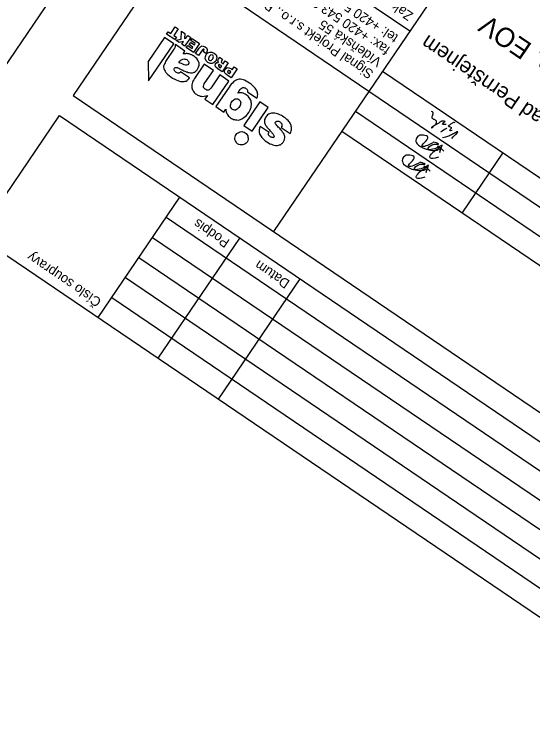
# Model space of a CAD drawing. Extents: x -621058 to -620110, y -1122807 to -1122030.
# Drawn here: x -621002.7 to -620949.2, y -1122263.7 to -1122190.1 of the extents above; entities that cross this region are included whole.
import ezdxf

# ---------------------------------------------------------------- set-up
doc = ezdxf.new("R2010")
doc.units = 0
for name, color, linetype in [('Default', 7, 'Continuous'), ('Info o rozpiskách', 7, 'Continuous'), ('LICHE', 7, 'Continuous'), ('Podpisy', 7, 'Continuous'), ('popis', 7, 'Continuous'), ('Ramečky', 7, 'Continuous'), ('RÁMY', 7, 'Continuous'), ('Text', 7, 'Continuous'), ('Text barevný', 7, 'Continuous')]:
    doc.layers.add(name, color=color, linetype=linetype)

# ---------------------------------------------------------------- blocks, each defined once
blk = doc.blocks.new('A$C65FD2E33_1')
at = {"layer": 'popis'}
for points in [[(-0.001696, 0.001402), (-0.001243, 0.00199), (-0.000783, 0.002198), (-0.00058, 0.001995), (-0.000655, 0.001241), (-0.001176, -0.000273), (-0.001696, 0.001402), (-0.001176, -0.000273)], [(0, 0), (0.000429, 0.000991), (0.001306, 0.001883), (0.000916, 0.000325), (0.00104, -0.00033), (0.00205, 0.000162), (0.002331, 0.000523), (0.002284, 0.001298), (0.001686, 0.001657), (0.000024, 0.001491), (-0.001834, 0.000276), (0, 0), (-0.001834, 0.000276)], [(-0.001176, -0.000273), (-0.00069, 0.000816), (0.000494, 0.001844), (0, 0), (-0.001176, -0.000273), (0, 0)]]:
    blk.add_open_spline(points, degree=3, dxfattribs=at)
blk = doc.blocks.new('podpis_vyvoda')
at = {"layer": 'Default'}
for points, degree in [([(0.027, 0.238), (0.019, 0.149), (-0.001, 0.052), (-0.009, -0.025), (0.03, 0.048), (0.089, 0.161), (0.154, 0.255), (0.197, 0.319), (0.239, 0.357)], 3), ([(0.289, 0.083), (0.328, 0.161), (0.348, 0.206), (0.366, 0.257)], 2), ([(0.361, 0.009), (0.395, 0.041), (0.415, 0.059), (0.44, 0.059), (0.446, 0.056), (0.449, 0.046), (0.448, 0.031), (0.447, 0.012), (0.439, -0.011), (0.429, -0.026), (0.425, -0.037), (0.431, -0.039), (0.466, -0.022), (0.498, 0), (0.518, 0.019), (0.527, 0.042), (0.531, 0.068), (0.542, 0.096), (0.556, 0.126), (0.582, 0.173), (0.6, 0.207), (0.62, 0.245), (0.63, 0.266), (0.634, 0.282), (0.636, 0.302), (0.629, 0.305), (0.62, 0.291), (0.614, 0.271), (0.61, 0.243), (0.596, 0.181), (0.594, 0.151), (0.596, 0.113), (0.605, 0.097), (0.62, 0.085), (0.645, 0.077), (0.675, 0.079), (0.701, 0.085), (0.734, 0.088), (0.757, 0.086), (0.775, 0.068), (0.783, 0.042), (0.788, 0.018), (0.795, -0.004), (0.804, -0.027), (0.816, -0.045), (0.832, -0.054), (0.848, -0.058), (0.874, -0.055)], 3), ([(0.141, 0.058), (0.176, 0.089), (0.196, 0.096), (0.203, 0.087), (0.195, 0.044), (0.19, 0.021), (0.197, 0.004), (0.217, 0.007), (0.27, 0.019), (0.283, 0.019), (0.288, 0.002), (0.28, -0.031), (0.269, -0.069), (0.243, -0.119), (0.227, -0.15), (0.219, -0.158), (0.203, -0.155)], 3)]:
    blk.add_open_spline(points, degree=degree, dxfattribs=at)

msp = doc.modelspace()

# ---------------------------------------------------------------- linework, layer by layer
at = {"layer": 'Info o rozpiskách'}
for points in [[(-620986.09, -1122192.714), (-620986.939, -1122192.137), (-620986.776, -1122191.898), (-620986.506, -1122192.081), (-620986.045, -1122191.402), (-620985.744, -1122191.607), (-620986.205, -1122192.286), (-620985.927, -1122192.474), (-620986.09, -1122192.714)], [(-620985.079, -1122193.4), (-620985.388, -1122193.191), (-620985.188, -1122192.897), (-620985.65, -1122193.012), (-620986.005, -1122192.771), (-620985.429, -1122192.654), (-620985.42, -1122191.827), (-620985.057, -1122192.073), (-620985.08, -1122192.588), (-620984.963, -1122192.566), (-620984.764, -1122192.272), (-620984.455, -1122192.482), (-620985.079, -1122193.4)], [(-620984.161, -1122194.024), (-620984.909, -1122193.515), (-620984.768, -1122193.307), (-620984.32, -1122193.611), (-620984.226, -1122193.472), (-620984.604, -1122193.215), (-620984.457, -1122192.999), (-620984.079, -1122193.256), (-620983.984, -1122193.117), (-620984.455, -1122192.797), (-620984.309, -1122192.581), (-620983.537, -1122193.105), (-620984.161, -1122194.024)], [(-620983.667, -1122194.359), (-620983.968, -1122194.155), (-620983.58, -1122193.584), (-620983.428, -1122193.427), (-620983.26, -1122193.361), (-620982.973, -1122193.454), (-620982.83, -1122193.575), (-620982.756, -1122193.715), (-620982.757, -1122193.883), (-620982.836, -1122194.066), (-620982.891, -1122194.13), (-620983.161, -1122193.947), (-620983.072, -1122193.782), (-620983.102, -1122193.694), (-620983.177, -1122193.688), (-620983.253, -1122193.749), (-620983.667, -1122194.359)], [(-620982.687, -1122195.058), (-620982.875, -1122194.886), (-620982.963, -1122194.668), (-620982.943, -1122194.456), (-620982.854, -1122194.257), (-620982.692, -1122194.085), (-620982.494, -1122193.994), (-620982.267, -1122193.991), (-620982.032, -1122194.094), (-620981.842, -1122194.279), (-620981.759, -1122194.505), (-620981.786, -1122194.711), (-620981.881, -1122194.918), (-620982.038, -1122195.082), (-620982.23, -1122195.166), (-620982.458, -1122195.169), (-620982.687, -1122195.058)], [(-620982.535, -1122194.834), (-620982.448, -1122194.871), (-620982.362, -1122194.862), (-620982.185, -1122194.7), (-620982.095, -1122194.468), (-620982.184, -1122194.317), (-620982.383, -1122194.295), (-620982.537, -1122194.439), (-620982.622, -1122194.663), (-620982.61, -1122194.761), (-620982.535, -1122194.834)], [(-620981.221, -1122196.02), (-620981.668, -1122195.716), (-620981.858, -1122195.565), (-620981.948, -1122195.414), (-620981.891, -1122195.182), (-620981.746, -1122195.066), (-620981.585, -1122195.062), (-620981.653, -1122194.881), (-620981.572, -1122194.711), (-620981.524, -1122194.641), (-620981.485, -1122194.567), (-620981.493, -1122194.528), (-620981.477, -1122194.504), (-620981.168, -1122194.714), (-620981.263, -1122194.887), (-620981.308, -1122195.07), (-620981.252, -1122195.12), (-620981.164, -1122195.19), (-620981.118, -1122195.222), (-620980.898, -1122194.898), (-620980.597, -1122195.102), (-620981.221, -1122196.02)], [(-620981.38, -1122195.608), (-620981.254, -1122195.422), (-620981.386, -1122195.333), (-620981.515, -1122195.291), (-620981.574, -1122195.329), (-620981.591, -1122195.419), (-620981.527, -1122195.508), (-620981.38, -1122195.608)], [(-620980.295, -1122196.649), (-620980.735, -1122196.351), (-620980.894, -1122196.22), (-620980.976, -1122196.074), (-620980.984, -1122195.921), (-620980.908, -1122195.759), (-620980.684, -1122195.595), (-620980.513, -1122195.61), (-620980.32, -1122195.707), (-620980.166, -1122195.812), (-620979.972, -1122195.526), (-620979.671, -1122195.731), (-620980.295, -1122196.649)], [(-620980.454, -1122196.237), (-620980.313, -1122196.028), (-620980.444, -1122195.939), (-620980.537, -1122195.91), (-620980.633, -1122195.968), (-620980.649, -1122196.059), (-620980.539, -1122196.179), (-620980.454, -1122196.237)], [(-620979.613, -1122203.449), (-620979.716, -1122203.368), (-620979.782, -1122203.267), (-620979.838, -1122203.15), (-620979.891, -1122203.012), (-620979.895, -1122202.886), (-620979.874, -1122202.754), (-620979.839, -1122202.62), (-620979.773, -1122202.506), (-620979.692, -1122202.403), (-620979.575, -1122202.314), (-620979.46, -1122202.245), (-620979.352, -1122202.217), (-620979.194, -1122202.2), (-620979.075, -1122202.225), (-620978.956, -1122202.249), (-620978.843, -1122202.315), (-620978.724, -1122202.407), (-620978.65, -1122202.513), (-620978.568, -1122202.625), (-620978.549, -1122202.763), (-620978.527, -1122202.879), (-620978.525, -1122203.027), (-620978.573, -1122203.163), (-620978.623, -1122203.287), (-620978.72, -1122203.38), (-620978.824, -1122203.466), (-620978.962, -1122203.52), (-620979.089, -1122203.557), (-620979.213, -1122203.574), (-620979.358, -1122203.555), (-620979.484, -1122203.526), (-620979.613, -1122203.449)]]:
    msp.add_lwpolyline(points, dxfattribs=at)
at = {"layer": 'popis'}
for points in [[(-620988.796, -1122196.965), (-620986.192, -1122193.129), (-620987.149, -1122192.479), (-620988.841, -1122194.972), (-620988.796, -1122196.965)], [(-620984.576, -1122196.662), (-620985.495, -1122196.038), (-620985.55, -1122196.103), (-620985.602, -1122196.146), (-620985.659, -1122196.164), (-620985.718, -1122196.168), (-620985.786, -1122196.168), (-620985.858, -1122196.141), (-620985.912, -1122196.105), (-620985.974, -1122196.063), (-620986.043, -1122196.016), (-620986.107, -1122195.96), (-620986.14, -1122195.893), (-620986.161, -1122195.857), (-620986.171, -1122195.805), (-620986.18, -1122195.753), (-620986.154, -1122195.714), (-620986.144, -1122195.665), (-620986.102, -1122195.637), (-620986.063, -1122195.596), (-620986.003, -1122195.591), (-620985.944, -1122195.587), (-620985.869, -1122195.592), (-620985.781, -1122195.63), (-620985.686, -1122195.672), (-620985.59, -1122195.714), (-620985.492, -1122195.769), (-620985.382, -1122195.822), (-620985.278, -1122195.869), (-620985.168, -1122195.922), (-620985.052, -1122195.967), (-620984.941, -1122196.02), (-620984.835, -1122196.046), (-620984.732, -1122196.094), (-620984.613, -1122196.118), (-620984.489, -1122196.135), (-620984.37, -1122196.125), (-620984.274, -1122196.134), (-620984.178, -1122196.109), (-620984.098, -1122196.073), (-620984.041, -1122196.056), (-620983.971, -1122196.002), (-620983.914, -1122195.951), (-620983.851, -1122195.892), (-620983.801, -1122195.835), (-620983.754, -1122195.766), (-620983.641, -1122195.549), (-620983.593, -1122195.345), (-620983.598, -1122195.138), (-620983.649, -1122194.98), (-620983.728, -1122194.814), (-620983.838, -1122194.66), (-620983.948, -1122194.54), (-620984.081, -1122194.438), (-620984.143, -1122194.397), (-620984.202, -1122194.367), (-620984.264, -1122194.326), (-620984.344, -1122194.294), (-620984.396, -1122194.27), (-620984.47, -1122194.231), (-620984.543, -1122194.204), (-620984.607, -1122194.183), (-620984.682, -1122194.177), (-620984.757, -1122194.171), (-620984.827, -1122194.158), (-620984.914, -1122194.154), (-620984.987, -1122194.161), (-620985.065, -1122194.177), (-620985.158, -1122194.181), (-620985.23, -1122194.188), (-620985.052, -1122193.892), (-620986.04, -1122193.221), (-620986.066, -1122193.26), (-620986.049, -1122193.35), (-620986.052, -1122193.405), (-620986.055, -1122193.459), (-620986.076, -1122193.49), (-620986.092, -1122193.547), (-620986.113, -1122193.578), (-620986.144, -1122193.624), (-620986.186, -1122193.685), (-620986.993, -1122194.874), (-620987.061, -1122194.974), (-620987.106, -1122195.09), (-620987.154, -1122195.193), (-620987.201, -1122195.296), (-620987.23, -1122195.389), (-620987.249, -1122195.467), (-620987.258, -1122195.562), (-620987.236, -1122195.679), (-620987.203, -1122195.78), (-620987.165, -1122195.874), (-620987.104, -1122195.983), (-620987.029, -1122196.09), (-620986.937, -1122196.186), (-620986.809, -1122196.296), (-620986.673, -1122196.411), (-620986.519, -1122196.549), (-620986.32, -1122196.673), (-620986.109, -1122196.794), (-620985.947, -1122196.87), (-620985.785, -1122196.946), (-620985.627, -1122196.997), (-620985.501, -1122197.026), (-620985.364, -1122197.041), (-620985.242, -1122197.044), (-620985.123, -1122197.035), (-620985.027, -1122197.01), (-620984.918, -1122196.982), (-620984.835, -1122196.926), (-620984.778, -1122196.875), (-620984.702, -1122196.814), (-620984.634, -1122196.747), (-620984.576, -1122196.662)], [(-620985.683, -1122195.087), (-620985.678, -1122195.079), (-620985.662, -1122195.056), (-620985.652, -1122195.041), (-620985.563, -1122194.943), (-620985.482, -1122194.84), (-620985.391, -1122194.789), (-620985.282, -1122194.728), (-620985.173, -1122194.701), (-620985.069, -1122194.714), (-620984.958, -1122194.733), (-620984.858, -1122194.768), (-620984.788, -1122194.815), (-620984.753, -1122194.862), (-620984.722, -1122194.917), (-620984.691, -1122194.971), (-620984.666, -1122195.034), (-620984.654, -1122195.098), (-620984.649, -1122195.158), (-620984.683, -1122195.225), (-620984.767, -1122195.315), (-620984.873, -1122195.355), (-620984.997, -1122195.339), (-620985.118, -1122195.302), (-620985.27, -1122195.243), (-620985.397, -1122195.18), (-620985.546, -1122195.135), (-620985.683, -1122195.087)], [(-620982.163, -1122199.417), (-620980.512, -1122196.986), (-620981.438, -1122196.357), (-620982.282, -1122197.6), (-620982.371, -1122197.731), (-620982.478, -1122197.839), (-620982.564, -1122197.882), (-620982.637, -1122197.923), (-620982.717, -1122197.925), (-620982.8, -1122197.914), (-620982.882, -1122197.869), (-620982.97, -1122197.832), (-620983.036, -1122197.764), (-620983.08, -1122197.712), (-620983.134, -1122197.642), (-620983.141, -1122197.569), (-620983.135, -1122197.494), (-620983.119, -1122197.404), (-620983.061, -1122197.285), (-620982.987, -1122197.177), (-620982.117, -1122195.896), (-620983.059, -1122195.257), (-620984.055, -1122196.723), (-620984.144, -1122196.854), (-620984.22, -1122196.983), (-620984.275, -1122197.114), (-620984.31, -1122197.249), (-620984.335, -1122197.368), (-620984.346, -1122197.484), (-620984.324, -1122197.6), (-620984.324, -1122197.702), (-620984.299, -1122197.797), (-620984.266, -1122197.898), (-620984.205, -1122197.974), (-620984.154, -1122198.065), (-620984.082, -1122198.159), (-620984.016, -1122198.227), (-620983.949, -1122198.294), (-620983.857, -1122198.357), (-620983.741, -1122198.436), (-620983.604, -1122198.484), (-620983.493, -1122198.536), (-620983.349, -1122198.556), (-620983.212, -1122198.57), (-620983.059, -1122198.561), (-620982.906, -1122198.518), (-620982.732, -1122198.478), (-620982.989, -1122198.857), (-620982.163, -1122199.417)], [(-620981.034, -1122200.195), (-620980.83, -1122199.894), (-620980.818, -1122200.026), (-620980.788, -1122200.148), (-620980.75, -1122200.275), (-620980.692, -1122200.405), (-620980.623, -1122200.52), (-620980.546, -1122200.606), (-620980.456, -1122200.689), (-620980.346, -1122200.775), (-620980.232, -1122200.841), (-620980.15, -1122200.886), (-620980.031, -1122200.944), (-620979.928, -1122200.958), (-620979.82, -1122200.997), (-620979.693, -1122200.993), (-620979.569, -1122201.01), (-620979.439, -1122200.985), (-620979.325, -1122200.95), (-620979.195, -1122200.892), (-620979.073, -1122200.828), (-620978.966, -1122200.754), (-620978.831, -1122200.654), (-620978.706, -1122200.536), (-620978.586, -1122200.392), (-620978.475, -1122200.23), (-620978.386, -1122200.099), (-620978.323, -1122199.973), (-620978.281, -1122199.844), (-620978.233, -1122199.707), (-620978.203, -1122199.581), (-620978.189, -1122199.443), (-620978.201, -1122199.311), (-620978.21, -1122199.192), (-620978.233, -1122199.076), (-620978.26, -1122198.967), (-620978.316, -1122198.85), (-620978.382, -1122198.749), (-620978.449, -1122198.647), (-620978.534, -1122198.556), (-620978.623, -1122198.472), (-620978.732, -1122198.399), (-620978.824, -1122198.336), (-620978.919, -1122198.294), (-620979.038, -1122198.236), (-620979.157, -1122198.211), (-620979.268, -1122198.192), (-620979.389, -1122198.189), (-620979.488, -1122198.201), (-620979.61, -1122198.231), (-620979.458, -1122198.007), (-620979.348, -1122197.845), (-620979.243, -1122197.758), (-620979.147, -1122197.699), (-620979.074, -1122197.658), (-620978.989, -1122197.649), (-620978.917, -1122197.675), (-620978.832, -1122197.699), (-620978.755, -1122197.752), (-620978.716, -1122197.778), (-620978.667, -1122197.822), (-620978.631, -1122197.869), (-620978.603, -1122197.911), (-620978.601, -1122197.957), (-620978.583, -1122198.014), (-620978.596, -1122198.051), (-620978.607, -1122198.1), (-620977.627, -1122198.765), (-620977.567, -1122198.626), (-620977.555, -1122198.51), (-620977.546, -1122198.38), (-620977.553, -1122198.274), (-620977.565, -1122198.142), (-620977.626, -1122198.033), (-620977.685, -1122197.937), (-620977.743, -1122197.807), (-620977.815, -1122197.713), (-620977.9, -1122197.622), (-620977.976, -1122197.536), (-620978.069, -1122197.44), (-620978.148, -1122197.374), (-620978.22, -1122197.314), (-620978.308, -1122197.243), (-620978.377, -1122197.196), (-620978.552, -1122197.088), (-620978.725, -1122196.994), (-620978.895, -1122196.912), (-620979.039, -1122196.859), (-620979.188, -1122196.814), (-620979.333, -1122196.795), (-620979.46, -1122196.799), (-620979.582, -1122196.829), (-620979.709, -1122196.866), (-620979.826, -1122196.922), (-620979.94, -1122196.991), (-620980.058, -1122197.081), (-620980.157, -1122197.194), (-620980.29, -1122197.307), (-620980.389, -1122197.453), (-620980.505, -1122197.623), (-620981.867, -1122199.629), (-620981.034, -1122200.195)], [(-620980.147, -1122199.918), (-620980.221, -1122199.845), (-620980.29, -1122199.764), (-620980.341, -1122199.673), (-620980.366, -1122199.577), (-620980.353, -1122199.474), (-620980.326, -1122199.368), (-620980.283, -1122199.239), (-620980.204, -1122199.123), (-620980.136, -1122199.023), (-620980.043, -1122198.951), (-620979.957, -1122198.874), (-620979.871, -1122198.832), (-620979.793, -1122198.816), (-620979.687, -1122198.81), (-620979.602, -1122198.834), (-620979.504, -1122198.889), (-620979.417, -1122198.959), (-620979.355, -1122199.035), (-620979.315, -1122199.141), (-620979.295, -1122199.211), (-620979.308, -1122199.315), (-620979.317, -1122199.411), (-620979.365, -1122199.514), (-620979.425, -1122199.619), (-620979.506, -1122199.722), (-620979.59, -1122199.812), (-620979.668, -1122199.894), (-620979.756, -1122199.958), (-620979.832, -1122199.986), (-620979.943, -1122200), (-620980.036, -1122199.971), (-620980.147, -1122199.918)], [(-620978.12, -1122202.163), (-620976.469, -1122199.732), (-620977.333, -1122199.145), (-620978.984, -1122201.577), (-620978.12, -1122202.163)], [(-620976.377, -1122202.287), (-620977.287, -1122201.669), (-620977.317, -1122201.761), (-620977.348, -1122201.842), (-620977.372, -1122201.926), (-620977.389, -1122202.017), (-620977.392, -1122202.105), (-620977.393, -1122202.206), (-620977.389, -1122202.299), (-620977.366, -1122202.416), (-620977.323, -1122202.501), (-620977.27, -1122202.605), (-620977.203, -1122202.707), (-620977.121, -1122202.819), (-620977.021, -1122202.92), (-620976.906, -1122203.033), (-620976.77, -1122203.148), (-620976.613, -1122203.265), (-620976.446, -1122203.368), (-620976.281, -1122203.457), (-620976.129, -1122203.516), (-620975.982, -1122203.581), (-620975.847, -1122203.616), (-620975.723, -1122203.633), (-620975.61, -1122203.631), (-620975.496, -1122203.63), (-620975.384, -1122203.615), (-620975.296, -1122203.585), (-620975.208, -1122203.554), (-620975.138, -1122203.501), (-620975.054, -1122203.444), (-620974.992, -1122203.386), (-620974.94, -1122203.342), (-620974.882, -1122203.257), (-620974.821, -1122203.118), (-620974.776, -1122202.968), (-620974.751, -1122202.849), (-620974.761, -1122202.697), (-620974.793, -1122202.595), (-620974.831, -1122202.468), (-620974.9, -1122202.354), (-620974.987, -1122202.25), (-620975.069, -1122202.138), (-620975.156, -1122202.034), (-620975.243, -1122201.929), (-620975.33, -1122201.825), (-620975.428, -1122201.736), (-620975.51, -1122201.658), (-620975.587, -1122201.572), (-620975.645, -1122201.475), (-620975.709, -1122201.387), (-620975.727, -1122201.33), (-620975.732, -1122201.27), (-620975.713, -1122201.227), (-620975.65, -1122201.168), (-620975.606, -1122201.153), (-620975.565, -1122201.125), (-620975.497, -1122201.125), (-620975.422, -1122201.131), (-620975.373, -1122201.142), (-620975.309, -1122201.163), (-620975.255, -1122201.2), (-620975.201, -1122201.236), (-620975.15, -1122201.294), (-620975.096, -1122201.364), (-620975.073, -1122201.413), (-620975.056, -1122201.504), (-620975.048, -1122201.576), (-620975.07, -1122201.674), (-620975.11, -1122201.783), (-620974.207, -1122202.396), (-620974.138, -1122202.262), (-620974.096, -1122202.133), (-620974.072, -1122202.014), (-620974.065, -1122201.906), (-620974.067, -1122201.792), (-620974.082, -1122201.68), (-620974.104, -1122201.564), (-620974.144, -1122201.458), (-620974.206, -1122201.348), (-620974.267, -1122201.239), (-620974.338, -1122201.145), (-620974.418, -1122201.047), (-620974.528, -1122200.96), (-620974.613, -1122200.869), (-620974.708, -1122200.793), (-620974.839, -1122200.704), (-620974.976, -1122200.622), (-620975.107, -1122200.533), (-620975.246, -1122200.473), (-620975.385, -1122200.412), (-620975.517, -1122200.357), (-620975.643, -1122200.327), (-620975.78, -1122200.313), (-620975.892, -1122200.294), (-620976.013, -1122200.29), (-620976.137, -1122200.307), (-620976.233, -1122200.332), (-620976.334, -1122200.365), (-620976.433, -1122200.411), (-620976.527, -1122200.482), (-620976.598, -1122200.57), (-620976.66, -1122200.662), (-620976.676, -1122200.685), (-620976.692, -1122200.708), (-620976.708, -1122200.732), (-620976.723, -1122200.755), (-620976.744, -1122200.786), (-620976.76, -1122200.809), (-620976.771, -1122200.824), (-620976.781, -1122200.84), (-620976.841, -1122200.945), (-620976.855, -1122201.049), (-620976.853, -1122201.163), (-620976.829, -1122201.259), (-620976.804, -1122201.354), (-620976.768, -1122201.469), (-620976.725, -1122201.554), (-620976.653, -1122201.648), (-620976.589, -1122201.737), (-620976.518, -1122201.831), (-620976.446, -1122201.924), (-620976.372, -1122201.997), (-620976.287, -1122202.089), (-620976.218, -1122202.169), (-620976.136, -1122202.248), (-620976.074, -1122202.323), (-620976.018, -1122202.406), (-620975.959, -1122202.469), (-620975.926, -1122202.537), (-620975.883, -1122202.589), (-620975.867, -1122202.633), (-620975.842, -1122202.695), (-620975.842, -1122202.729), (-620975.863, -1122202.759), (-620975.884, -1122202.79), (-620975.921, -1122202.811), (-620975.972, -1122202.821), (-620976.014, -1122202.815), (-620976.066, -1122202.825), (-620976.12, -1122202.789), (-620976.192, -1122202.762), (-620976.246, -1122202.725), (-620976.308, -1122202.683), (-620976.351, -1122202.631), (-620976.392, -1122202.592), (-620976.423, -1122202.537), (-620976.427, -1122202.478), (-620976.417, -1122202.429), (-620976.416, -1122202.362), (-620976.377, -1122202.287)]]:
    msp.add_lwpolyline(points, dxfattribs=at)
at = {"layer": 'Ramečky'}
for p, q in [((-620972.705, -1122163.327), (-620996.583, -1122198.486)), ((-620952.024, -1122177.373), (-620975.901, -1122212.531)), ((-620961.856, -1122191.85), (-620982.537, -1122177.804)), ((-620910.893, -1122232.505), (-620964.665, -1122195.986)), ((-620912.297, -1122234.573), (-620966.069, -1122198.054)), ((-620996.583, -1122198.486), (-620922.129, -1122249.05)), ((-620913.702, -1122236.641), (-620967.474, -1122200.123)), ((-621006.414, -1122212.963), (-620997.987, -1122200.554)), ((-620997.987, -1122200.554), (-620923.534, -1122251.118)), ((-620915.107, -1122238.709), (-620968.878, -1122202.191)), ((-620994.006, -1122221.39), (-620985.578, -1122208.981)), ((-620986.983, -1122211.05), (-620924.938, -1122253.186)), ((-621006.414, -1122212.963), (-620931.961, -1122263.527)), ((-620988.387, -1122213.118), (-620926.343, -1122255.254)), ((-620987.801, -1122225.604), (-620979.374, -1122213.195)), ((-620989.792, -1122215.186), (-620927.748, -1122257.322)), ((-620991.197, -1122217.254), (-620929.152, -1122259.391)), ((-620981.597, -1122229.818), (-620973.169, -1122217.409)), ((-620992.601, -1122219.322), (-620930.557, -1122261.459))]:
    msp.add_line(p, q, dxfattribs=at)
for points in [[(-620966.069, -1122198.054), (-620986.751, -1122184.009)], [(-620956.47, -1122210.618), (-620952.256, -1122204.414)]]:
    msp.add_lwpolyline(points, dxfattribs=at)
at = {"layer": 'RÁMY'}
msp.add_lwpolyline([(-620974.696, -1122152.909), (-620192.937, -1122683.831), (-620276.367, -1122806.679), (-621058.127, -1122275.757)], close=True, dxfattribs=at)

# ---------------------------------------------------------------- block references
at = {"layer": 'LICHE', "xscale": 3.918060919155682, "yscale": 3.9180609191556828, "rotation": 145.81810353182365}
msp.add_blockref('podpis_vyvoda', (-620956.906, -1122202.22), dxfattribs=at)
at = {"layer": 'Podpisy', "xscale": 744.8335616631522, "yscale": 744.8335616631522, "rotation": 145.81811799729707}
for p in [(-620959.361, -1122203.277), (-620960.766, -1122205.345)]:
    msp.add_blockref('A$C65FD2E33_1', p, dxfattribs=at)

# ---------------------------------------------------------------- texts
at = {"layer": 'Text'}
for s, p in [('Zak. číslo zhotov.', (-620961.431, -1122190.023)), ('tel: +420 543 233 962', (-620962.968, -1122192.303)), ('fax: +420 543 331 046', (-620963.811, -1122193.544)), ('Signal Projekt s.r.o., Brno', (-620965.504, -1122196.021)), ('Vídeňská 55', (-620964.661, -1122194.78)), ('Podpis', (-620980.354, -1122213.436)), ('Číslo soupravy', (-620993.581, -1122219.563)), ('Datum', (-620974.149, -1122217.65))]:
    msp.add_text(s, height=1, rotation=145.81812, dxfattribs=at).set_placement(p)
at = {"layer": 'Text barevný'}
for s, height, p in [('SO 06-06-01 Bystřice nad Pernštějnem, EOV', 2, (-620909.42, -1122220.208)), ('Oprava zabezpečovacího zařízení v ŽST Bystřice nad Pernštejnem', 1.55893, (-620908.625, -1122227.042))]:
    msp.add_text(s, height=height, rotation=145.81812, dxfattribs=at).set_placement(p)

doc.saveas('drawing.dxf')
